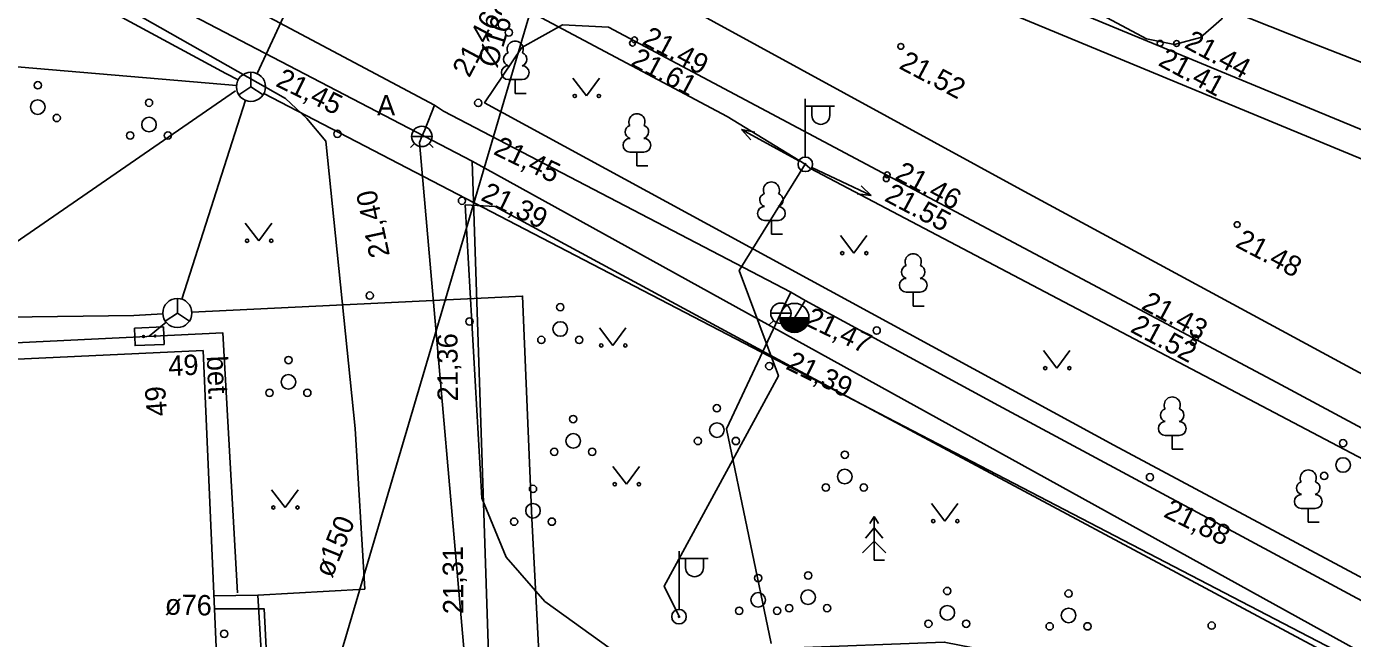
# Model space of a CAD drawing. Extents: x 714038 to 714279, y 6589845 to 6590041.
# Drawn here: x 714070.69 to 714116.25, y 6589966.53 to 6589987.55 of the extents above; entities that cross this region are included whole.
import ezdxf

# ---------------------------------------------------------------- set-up
doc = ezdxf.new("R2010")
doc.units = 0
for name, color, linetype in [('HALJASTUS', 7, 'Continuous'), ('HOONE', 7, 'Continuous'), ('HOONEDET', 7, 'Continuous'), ('KORGUS', 7, 'Continuous'), ('KTRASS', 7, 'Continuous'), ('MPKAABEL', 7, 'Continuous'), ('MPOHULIIN', 7, 'Continuous'), ('POST', 7, 'Continuous'), ('PUU', 7, 'Continuous'), ('SIKAEV', 7, 'Continuous'), ('SITRASS', 7, 'Continuous'), ('TEE', 7, 'Continuous'), ('TORU NR', 7, 'Continuous'), ('VKAEV', 7, 'Continuous'), ('VTRASS', 7, 'Continuous'), ('Слой 1', 7, 'Continuous')]:
    doc.layers.add(name, color=color, linetype=linetype)

msp = doc.modelspace()

# ---------------------------------------------------------------- linework, layer by layer
at = {"layer": 'HALJASTUS'}
for p, q in [((714089.464, 6589985.776), (714089.927, 6589985.169)), ((714089.927, 6589985.169), (714090.373, 6589985.776)), ((714078.206, 6589980.801), (714078.669, 6589980.195)), ((714078.669, 6589980.195), (714079.115, 6589980.801)), ((714098.654, 6589980.376), (714099.117, 6589979.769)), ((714099.117, 6589979.769), (714099.563, 6589980.376)), ((714090.371, 6589977.204), (714090.835, 6589976.598)), ((714090.835, 6589976.598), (714091.28, 6589977.204)), ((714105.63, 6589976.422), (714106.093, 6589975.816)), ((714106.093, 6589975.816), (714106.539, 6589976.422)), ((714090.838, 6589972.436), (714091.302, 6589971.829)), ((714091.302, 6589971.829), (714091.747, 6589972.436)), ((714079.107, 6589971.637), (714079.57, 6589971.03)), ((714079.57, 6589971.03), (714080.016, 6589971.637)), ((714101.78, 6589971.169), (714102.244, 6589970.562)), ((714102.244, 6589970.562), (714102.689, 6589971.169))]:
    msp.add_line(p, q, dxfattribs=at)
for centre, radius in [((714071.075, 6589985.537), 0.125), ((714071.075, 6589984.787), 0.25), ((714074.897, 6589984.936), 0.125), ((714089.526, 6589985.169), 0.055), ((714090.355, 6589985.169), 0.055), ((714071.725, 6589984.412), 0.125), ((714074.897, 6589984.186), 0.25), ((714074.247, 6589983.811), 0.125), ((714075.547, 6589983.811), 0.125), ((714078.268, 6589980.195), 0.055), ((714079.097, 6589980.195), 0.055), ((714098.716, 6589979.769), 0.055), ((714099.545, 6589979.769), 0.055), ((714089.027, 6589977.913), 0.125), ((714089.027, 6589977.163), 0.25), ((714088.377, 6589976.788), 0.125), ((714089.677, 6589976.788), 0.125), ((714090.434, 6589976.598), 0.055), ((714091.263, 6589976.598), 0.055), ((714079.687, 6589976.095), 0.125), ((714105.692, 6589975.816), 0.055), ((714106.521, 6589975.816), 0.055), ((714079.687, 6589975.345), 0.25), ((714079.037, 6589974.97), 0.125), ((714080.337, 6589974.97), 0.125), ((714094.408, 6589974.44), 0.125), ((714089.472, 6589974.068), 0.125), ((714094.408, 6589973.69), 0.25), ((714089.472, 6589973.318), 0.25), ((714088.822, 6589972.943), 0.125), ((714090.122, 6589972.943), 0.125), ((714093.758, 6589973.315), 0.125), ((714095.058, 6589973.315), 0.125), ((714115.925, 6589973.239), 0.125), ((714098.804, 6589972.843), 0.125), ((714115.925, 6589972.489), 0.25), ((714098.804, 6589972.093), 0.25), ((714115.275, 6589972.114), 0.125), ((714088.09, 6589971.668), 0.125), ((714090.901, 6589971.829), 0.055), ((714091.73, 6589971.829), 0.055), ((714098.154, 6589971.718), 0.125), ((714099.454, 6589971.718), 0.125), ((714088.09, 6589970.918), 0.25), ((714079.169, 6589971.03), 0.055), ((714079.998, 6589971.03), 0.055), ((714087.44, 6589970.543), 0.125), ((714088.74, 6589970.543), 0.125), ((714101.843, 6589970.562), 0.055), ((714102.672, 6589970.562), 0.055), ((714095.827, 6589968.606), 0.125), ((714097.544, 6589968.696), 0.125), ((714095.827, 6589967.856), 0.25), ((714097.544, 6589967.946), 0.25), ((714102.326, 6589968.162), 0.125), ((714106.494, 6589968.072), 0.125), ((714095.177, 6589967.481), 0.125), ((714096.477, 6589967.481), 0.125), ((714096.894, 6589967.571), 0.125), ((714098.194, 6589967.571), 0.125), ((714102.326, 6589967.412), 0.25), ((714106.494, 6589967.322), 0.25), ((714101.676, 6589967.037), 0.125), ((714102.976, 6589967.037), 0.125), ((714105.844, 6589966.947), 0.125), ((714107.144, 6589966.947), 0.125), ((714111.41, 6589966.972), 0.125)]:
    msp.add_circle(centre, radius, dxfattribs=at)
at = {"layer": 'HOONE'}
for points in [[(714037.81, 6590017.576), (714059.08, 6590006.51), (714072.38, 6589999.69), (714082.14, 6589994.37), (714104.85, 6589981.96), (714150.21, 6589957.43), (714183.55, 6589939.45), (714202.68, 6589928.99), (714214.04, 6589922.75), (714222.92, 6589918.06), (714237.47, 6589910.29), (714252.27, 6589902.23), (714256.602, 6589899.815), (714258.577, 6589898.715), (714261.69, 6589896.98)], [(714076.752, 6589976.421), (714079.42, 6589915.82), (714068.72, 6589915.35), (714065.699, 6589975.906), (714076.752, 6589976.421)], [(714079.4, 6589956.78), (714078.85, 6589967.55), (714077.14, 6589967.55)]]:
    msp.add_lwpolyline(points, dxfattribs=at)
at = {"layer": 'HOONEDET'}
for points in [[(714064.17, 6589960.69), (714063.83, 6589966.94), (714065.59, 6589967.14), (714065.32, 6589976.45), (714077.437, 6589977.031), (714077.942, 6589968.099)], [(714077.12, 6589967.99), (714078.64, 6589968.02), (714078.81, 6589965.13), (714077.25, 6589965.13)]]:
    msp.add_lwpolyline(points, dxfattribs=at)
at = {"layer": 'KORGUS'}
for centre, radius in [((714087.26, 6589987.35), 0.125), ((714091.576, 6589987.095), 0.1), ((714091.511, 6589986.982), 0.1), ((714100.729, 6589986.873), 0.1), ((714109.64, 6589986.978), 0.1), ((714110.206, 6589986.972), 0.1), ((714086.21, 6589984.93), 0.125), ((714081.37, 6589983.87), 0.125), ((714100.263, 6589982.457), 0.1), ((714100.23, 6589982.326), 0.1), ((714085.65, 6589981.57), 0.125), ((714112.287, 6589980.748), 0.1), ((714082.48, 6589978.31), 0.125), ((714085.91, 6589977.42), 0.125), ((714099.9, 6589977.11), 0.125), ((714110.777, 6589976.702), 0.1), ((714110.857, 6589976.856), 0.1), ((714096.21, 6589975.89), 0.125), ((714109.29, 6589972.07), 0.125), ((714077.48, 6589966.69), 0.125)]:
    msp.add_circle(centre, radius, dxfattribs=at)
at = {"layer": 'KTRASS'}
msp.add_lwpolyline([(714082.125, 6589929.177), (714081.284, 6589949.55), (714080.742, 6589963.482), (714093.581, 6590006.995)], dxfattribs=at)
at = {"layer": 'MPKAABEL'}
for points in [[(714037.81, 6590016.164), (714045.98, 6590012.32), (714093.89, 6589992.4), (714122, 6589980.75)], [(714097.447, 6589982.821), (714094.758, 6589984.46), (714071.268, 6589996.96), (714071.088, 6589997.05)], [(714093.108, 6589967.28), (714092.592, 6589968.332), (714096.522, 6589975.55), (714095.174, 6589979.174), (714097.447, 6589982.821)], [(714124.725, 6589968.419), (714097.597, 6589982.691), (714097.447, 6589982.821)]]:
    msp.add_lwpolyline(points, dxfattribs=at)
at = {"layer": 'MPOHULIIN'}
for p, q in [((714095.249, 6589984.012), (714095.574, 6589983.665)), ((714095.249, 6589984.012), (714095.717, 6589983.927)), ((714097.227, 6589982.94), (714095.249, 6589984.012)), ((714097.673, 6589982.714), (714099.705, 6589981.749)), ((714099.705, 6589981.749), (714099.233, 6589981.808)), ((714099.705, 6589981.749), (714099.362, 6589982.078))]:
    msp.add_line(p, q, dxfattribs=at)
at = {"layer": 'POST'}
for p, q in [((714097.447, 6589983.071), (714097.447, 6589985.071)), ((714097.447, 6589984.821), (714098.447, 6589984.821)), ((714097.673, 6589984.5), (714097.673, 6589984.821)), ((714098.286, 6589984.5), (714098.286, 6589984.821)), ((714093.108, 6589967.53), (714093.108, 6589969.53)), ((714093.108, 6589969.28), (714094.108, 6589969.28)), ((714093.335, 6589968.959), (714093.335, 6589969.28)), ((714093.948, 6589968.959), (714093.948, 6589969.28))]:
    msp.add_line(p, q, dxfattribs=at)
msp.add_lwpolyline([(714074.394, 6589977.193), (714075.393, 6589977.233), (714075.417, 6589976.633), (714074.418, 6589976.593)], close=True, dxfattribs=at)
for centre, radius in [((714097.447, 6589982.821), 0.25), ((714097.447, 6589982.821), 0.0234), ((714074.706, 6589976.905), 0.0304), ((714074.706, 6589976.905), 0.029), ((714074.706, 6589976.905), 0.0277), ((714074.706, 6589976.905), 0.0263), ((714074.706, 6589976.905), 0.0249), ((714074.706, 6589976.905), 0.0236), ((714074.706, 6589976.905), 0.0222), ((714074.706, 6589976.905), 0.0209), ((714074.706, 6589976.905), 0.0195), ((714074.706, 6589976.905), 0.0181), ((714074.706, 6589976.905), 0.0168), ((714074.706, 6589976.905), 0.0154), ((714074.706, 6589976.905), 0.014), ((714074.706, 6589976.905), 0.0127), ((714074.706, 6589976.905), 0.0113), ((714074.706, 6589976.905), 0.00996), ((714074.706, 6589976.905), 0.0086), ((714074.706, 6589976.905), 0.00724), ((714074.706, 6589976.905), 0.00587), ((714074.706, 6589976.905), 0.00451), ((714074.706, 6589976.905), 0.00315), ((714074.706, 6589976.905), 0.00179), ((714074.706, 6589976.905), 0.000426), ((714075.105, 6589976.921), 0.0304), ((714075.105, 6589976.921), 0.029), ((714075.105, 6589976.921), 0.0277), ((714075.105, 6589976.921), 0.0263), ((714075.105, 6589976.921), 0.0249), ((714075.105, 6589976.921), 0.0236), ((714075.105, 6589976.921), 0.0222), ((714075.105, 6589976.921), 0.0209), ((714075.105, 6589976.921), 0.0195), ((714075.105, 6589976.921), 0.0181), ((714075.105, 6589976.921), 0.0168), ((714075.105, 6589976.921), 0.0154), ((714075.105, 6589976.921), 0.014), ((714075.105, 6589976.921), 0.0127), ((714075.105, 6589976.921), 0.0113), ((714075.105, 6589976.921), 0.00996), ((714075.105, 6589976.921), 0.0086), ((714075.105, 6589976.921), 0.00724), ((714075.105, 6589976.921), 0.00587), ((714075.105, 6589976.921), 0.00451), ((714075.105, 6589976.921), 0.00315), ((714075.105, 6589976.921), 0.00179), ((714075.105, 6589976.921), 0.000426), ((714093.108, 6589967.28), 0.25), ((714093.108, 6589967.28), 0.0234)]:
    msp.add_circle(centre, radius, dxfattribs=at)
for centre in [(714097.98, 6589984.5), (714093.641, 6589968.959)]:
    msp.add_arc(centre, 0.306, 180, 0, dxfattribs=at)
at = {"layer": 'PUU'}
for p, q in [((714087.719, 6589985.733), (714087.239, 6589985.733)), ((714087.479, 6589985.258), (714087.479, 6589985.733)), ((714087.859, 6589985.258), (714087.479, 6589985.258)), ((714091.901, 6589983.238), (714091.421, 6589983.238)), ((714091.661, 6589982.763), (714091.661, 6589983.238)), ((714092.041, 6589982.763), (714091.661, 6589982.763)), ((714096.522, 6589980.894), (714096.042, 6589980.894)), ((714096.282, 6589980.419), (714096.282, 6589980.894)), ((714096.662, 6589980.419), (714096.282, 6589980.419)), ((714101.394, 6589978.426), (714100.914, 6589978.426)), ((714101.154, 6589977.951), (714101.154, 6589978.426)), ((714101.534, 6589977.951), (714101.154, 6589977.951)), ((714110.295, 6589973.506), (714109.815, 6589973.506)), ((714110.055, 6589973.031), (714110.055, 6589973.506)), ((714110.435, 6589973.031), (714110.055, 6589973.031)), ((714099.811, 6589970.726), (714099.661, 6589970.476)), ((714099.961, 6589970.476), (714099.811, 6589970.726)), ((714099.811, 6589970.726), (714099.811, 6589969.226)), ((714114.969, 6589970.999), (714114.489, 6589970.999)), ((714114.729, 6589970.524), (714114.729, 6589970.999)), ((714099.811, 6589970.326), (714099.511, 6589969.976)), ((714100.111, 6589969.976), (714099.811, 6589970.326)), ((714115.109, 6589970.524), (714114.729, 6589970.524)), ((714099.811, 6589969.876), (714099.411, 6589969.476)), ((714100.211, 6589969.476), (714099.811, 6589969.876)), ((714100.171, 6589969.226), (714099.811, 6589969.226))]:
    msp.add_line(p, q, dxfattribs=at)
for centre, radius, start, end in [((714087.479, 6589986.778), 0.277, 332.5799, 207.4201), ((714087.241, 6589985.97), 0.238, 90.0016, 269.3953), ((714087.309, 6589986.431), 0.233, 109.0217, 253.1415), ((714087.649, 6589986.431), 0.233, 286.8508, 70.9859), ((714087.716, 6589985.97), 0.238, 270.6047, 89.9984), ((714091.661, 6589984.283), 0.277, 332.5799, 207.4201), ((714091.491, 6589983.935), 0.233, 109.0217, 253.1415), ((714091.831, 6589983.935), 0.233, 286.8508, 70.9859), ((714091.424, 6589983.475), 0.238, 90.0016, 269.3953), ((714091.899, 6589983.475), 0.238, 270.6047, 89.9984), ((714096.282, 6589981.939), 0.277, 332.5799, 207.4201), ((714096.112, 6589981.592), 0.233, 109.0217, 253.1415), ((714096.452, 6589981.592), 0.233, 286.8508, 70.9859), ((714096.044, 6589981.132), 0.238, 90.0016, 269.3953), ((714096.519, 6589981.132), 0.238, 270.6047, 89.9984), ((714101.154, 6589979.471), 0.277, 332.5799, 207.4201), ((714100.984, 6589979.124), 0.233, 109.0217, 253.1415), ((714101.324, 6589979.124), 0.233, 286.8508, 70.9859), ((714100.917, 6589978.664), 0.238, 90.0016, 269.3953), ((714101.392, 6589978.664), 0.238, 270.6047, 89.9984), ((714110.055, 6589974.551), 0.277, 332.5799, 207.4201), ((714109.885, 6589974.203), 0.233, 109.0217, 253.1415), ((714110.225, 6589974.203), 0.233, 286.8508, 70.9859), ((714109.817, 6589973.743), 0.238, 90.0016, 269.3953), ((714110.292, 6589973.743), 0.238, 270.6047, 89.9984), ((714114.729, 6589972.044), 0.277, 332.5799, 207.4201), ((714114.559, 6589971.697), 0.233, 109.0217, 253.1415), ((714114.899, 6589971.697), 0.233, 286.8508, 70.9859), ((714114.492, 6589971.237), 0.238, 90.0016, 269.3953), ((714114.967, 6589971.237), 0.238, 270.6047, 89.9984)]:
    msp.add_arc(centre, radius, start, end, dxfattribs=at)
at = {"layer": 'SIKAEV'}
for p, q in [((714078.399, 6589985.984), (714078.399, 6589985.484)), ((714078.399, 6589985.484), (714077.984, 6589985.209)), ((714078.399, 6589985.484), (714078.814, 6589985.209)), ((714075.87, 6589978.212), (714075.87, 6589977.712)), ((714075.87, 6589977.712), (714075.455, 6589977.437)), ((714075.87, 6589977.712), (714076.285, 6589977.437))]:
    msp.add_line(p, q, dxfattribs=at)
for centre in [(714078.399, 6589985.484), (714075.87, 6589977.712)]:
    msp.add_circle(centre, 0.5, dxfattribs=at)
at = {"layer": 'SITRASS'}
for points in [[(714078.609, 6589985.937), (714086.299, 6590002.484), (714089.168, 6590008.661), (714094.05, 6590020), (714095.092, 6590022.185), (714097.899, 6590028.624), (714100.251, 6590033.606)], [(714037.81, 6590017.083), (714041.45, 6590015.4), (714049.64, 6590011.61), (714053.69, 6590009.84), (714078.46, 6589999.77), (714120.53, 6589982.37), (714120.99, 6589982.37), (714121.09, 6589982.42), (714121.19, 6589982.57), (714121.29, 6589982.87), (714121.49, 6589988.215), (714121.85, 6589997.82), (714121.9, 6589998.22), (714123.574, 6590001.009)], [(714077.958, 6589985.72), (714077.539, 6589985.944), (714055.281, 6589997.97), (714037.81, 6590007.322)], [(714060.942, 6589986.97), (714077.9, 6589985.526)], [(714066.52, 6589977.52), (714077.87, 6589985.346)], [(714076.023, 6589978.188), (714078.215, 6589985.019)], [(714127.986, 6589959.082), (714115.909, 6589965.994), (714078.842, 6589985.253)], [(714090.77, 6589947.71), (714089.15, 6589947.61), (714088.441, 6589963.198), (714088.049, 6589970.65), (714087.73, 6589978.292), (714076.369, 6589977.736)], [(714075.371, 6589977.682), (714074.38, 6589977.623), (714066.51, 6589977.52), (714053.4, 6589976.7), (714054.32, 6589939.62), (714054.67, 6589922.8)], [(714074.906, 6589976.913), (714075.485, 6589977.393)]]:
    msp.add_lwpolyline(points, dxfattribs=at)
at = {"layer": 'TEE'}
msp.add_lwpolyline([(714111.749, 6589987.81), (714112.752, 6589989.647), (714101.456, 6589995.811), (714078.958, 6590007.942), (714056.863, 6590019.705), (714055.67, 6590019.684), (714056.126, 6590016.909), (714056.904, 6590015.524), (714058.111, 6590014.408), (714066.132, 6590010.156), (714094.483, 6589994.979), (714109.175, 6589987.135), (714110.128, 6589986.933), (714111.028, 6589987.18)], close=True, dxfattribs=at)
for points in [[(714051.575, 6589993.973), (714051.436, 6589997.034), (714052.061, 6589999.007), (714052.983, 6589999.515), (714074.327, 6589988.058), (714079.586, 6589985.085), (714080.323, 6589984.396)], [(714123.973, 6589969.784), (714113.651, 6589975.327), (714090.687, 6589987.533), (714089.1, 6589987.616), (714087.707, 6589986.834), (714086.427, 6589984.934), (714108.053, 6589973.169), (714127.373, 6589962.843)], [(714078.64, 6589968.02), (714082.311, 6589968.226), (714081.98, 6589973.746), (714080.975, 6589983.611), (714080.323, 6589984.396)], [(714117.751, 6589964.757), (714096.936, 6589975.889), (714086.792, 6589981.374), (714085.763, 6589981.428), (714086.329, 6589971.355), (714087.167, 6589969.326), (714088.497, 6589967.804), (714090.737, 6589966.182), (714091.388, 6589965.99), (714102.223, 6589966.405), (714103.211, 6589966.21), (714105.25, 6589963.96), (714106.305, 6589963.671), (714118.34, 6589963.691)]]:
    msp.add_lwpolyline(points, dxfattribs=at)
at = {"layer": 'VKAEV'}
for p, q in [((714084.024, 6589983.533), (714083.884, 6589983.393)), ((714083.921, 6589983.78), (714084.621, 6589983.78)), ((714084.518, 6589983.533), (714084.658, 6589983.393)), ((714096.257, 6589977.702), (714096.957, 6589977.702)), ((714096.573, 6589977.544), (714097.573, 6589977.544)), ((714096.36, 6589977.455), (714096.22, 6589977.315)), ((714096.854, 6589977.455), (714096.994, 6589977.315))]:
    msp.add_line(p, q, dxfattribs=at)
for centre, radius in [((714084.271, 6589983.78), 0.35), ((714096.607, 6589977.702), 0.35), ((714097.073, 6589977.544), 0.5)]:
    msp.add_circle(centre, radius, dxfattribs=at)
for radius in [0.483, 0.468, 0.45, 0.435, 0.418, 0.403, 0.386, 0.371, 0.354, 0.339, 0.321, 0.306, 0.289, 0.274, 0.257, 0.242, 0.224, 0.209, 0.192, 0.177, 0.16, 0.145, 0.127, 0.112, 0.0951, 0.0801, 0.0628, 0.0478, 0.0328, 0.0178]:
    msp.add_arc((714097.073, 6589977.544), radius, 180, 0, dxfattribs=at)
at = {"layer": 'VTRASS'}
for points in [[(714153.798, 6589949.498), (714152.517, 6589948.338), (714134.349, 6589958.294), (714134.144, 6589958.409), (714120.209, 6589965.86), (714104.085, 6589974.529), (714097.438, 6589978.146), (714096.95, 6589978.424), (714085.013, 6589984.641), (714084.705, 6589984.858), (714077.379, 6589988.763), (714061.877, 6589996.73), (714043.432, 6590006.628), (714037.81, 6590009.751)], [(714102.729, 6589991.799), (714114.744, 6589987.033), (714134.634, 6589979.269)], [(714084.705, 6589984.858), (714084.377, 6589984.01), (714084.271, 6589983.78)], [(714084.271, 6589983.78), (714084.196, 6589983.57), (714086.016, 6589962.801), (714087.111, 6589942.079)], [(714096.95, 6589978.424), (714096.658, 6589977.845), (714096.607, 6589977.702)], [(714097.438, 6589978.146), (714097.251, 6589977.819), (714097.073, 6589977.544)], [(714096.607, 6589977.702), (714094.74, 6589973.737), (714096.273, 6589966.363)]]:
    msp.add_lwpolyline(points, dxfattribs=at)
at = {"layer": 'Слой 1'}
for points in [[(714064.59, 6589902.42), (714061.29, 6589975.82), (714066.29, 6589976.05), (714066.53, 6589993.08), (714086, 6589982.93), (714087.46, 6589939.06), (714088.9, 6589899.98), (714072.76, 6589898.26)], [(714086, 6589982.93), (714135.78, 6589955.43), (714136.17, 6589942.13), (714118.41, 6589940.84), (714087.46, 6589939.06)]]:
    msp.add_lwpolyline(points, close=True, dxfattribs=at)

# ---------------------------------------------------------------- texts
at = {"layer": 'HOONE'}
for rotation, p in [(2.582, (714075.573, 6589975.546)), (94.4787, (714075.525, 6589974.186))]:
    msp.add_text('49', height=0.7, rotation=rotation, dxfattribs=at).set_placement(p)
at = {"layer": 'HOONEDET'}
msp.add_text('bet.', height=0.7, rotation=272.5859, dxfattribs=at).set_placement((714076.879, 6589976.229))
at = {"layer": 'KORGUS'}
for s, rotation, p in [('21,46', 62.0266, (714085.9, 6589985.769)), (' 21.49', 331.8975, (714091.576, 6589987.095)), (' 21.44', 331.6624, (714110.206, 6589986.972)), (' 21.61', 331.8975, (714091.181, 6589986.365)), (' 21.52', 332.171, (714100.402, 6589986.254)), (' 21.41', 331.6624, (714109.308, 6589986.362)), ('21,45', 334.0139, (714079.215, 6589985.524)), ('21,45', 334.0139, (714086.695, 6589983.184)), (' 21.46', 331.932, (714100.263, 6589982.457)), ('21,39', 334.0139, (714086.261, 6589981.606)), (' 21.55', 331.932, (714099.901, 6589981.708)), ('21,40', 102.0407, (714083.176, 6589979.692)), (' 21.48', 332.171, (714111.96, 6589980.129)), (' 21.43', 331.932, (714108.726, 6589977.992)), ('21,47', 334.0139, (714097.395, 6589977.314)), (' 21.52', 331.932, (714108.348, 6589977.204)), ('21,36', 90.4705, (714085.512, 6589974.677)), ('21,39', 334.0139, (714096.741, 6589975.806)), ('21,88', 334.0139, (714109.721, 6589970.726)), ('21,31', 90.4705, (714085.701, 6589967.369))]:
    msp.add_text(s, height=0.7, rotation=rotation, dxfattribs=at).set_placement(p)
at = {"layer": 'KTRASS'}
msp.add_text('%%c160 PE', height=0.7, rotation=72.4078, dxfattribs=at).set_placement((714086.838, 6589986.099))
at = {"layer": 'TEE'}
msp.add_text('A', height=0.7, dxfattribs=at).set_placement((714082.732, 6589984.498))
at = {"layer": 'TORU NR'}
for s, rotation, p in [('ø150', 67.8564, (714081.183, 6589968.58)), ('ø76', 358.8423, (714075.436, 6589967.351))]:
    msp.add_text(s, height=0.7, rotation=rotation, dxfattribs=at).set_placement(p)

doc.saveas('drawing.dxf')
